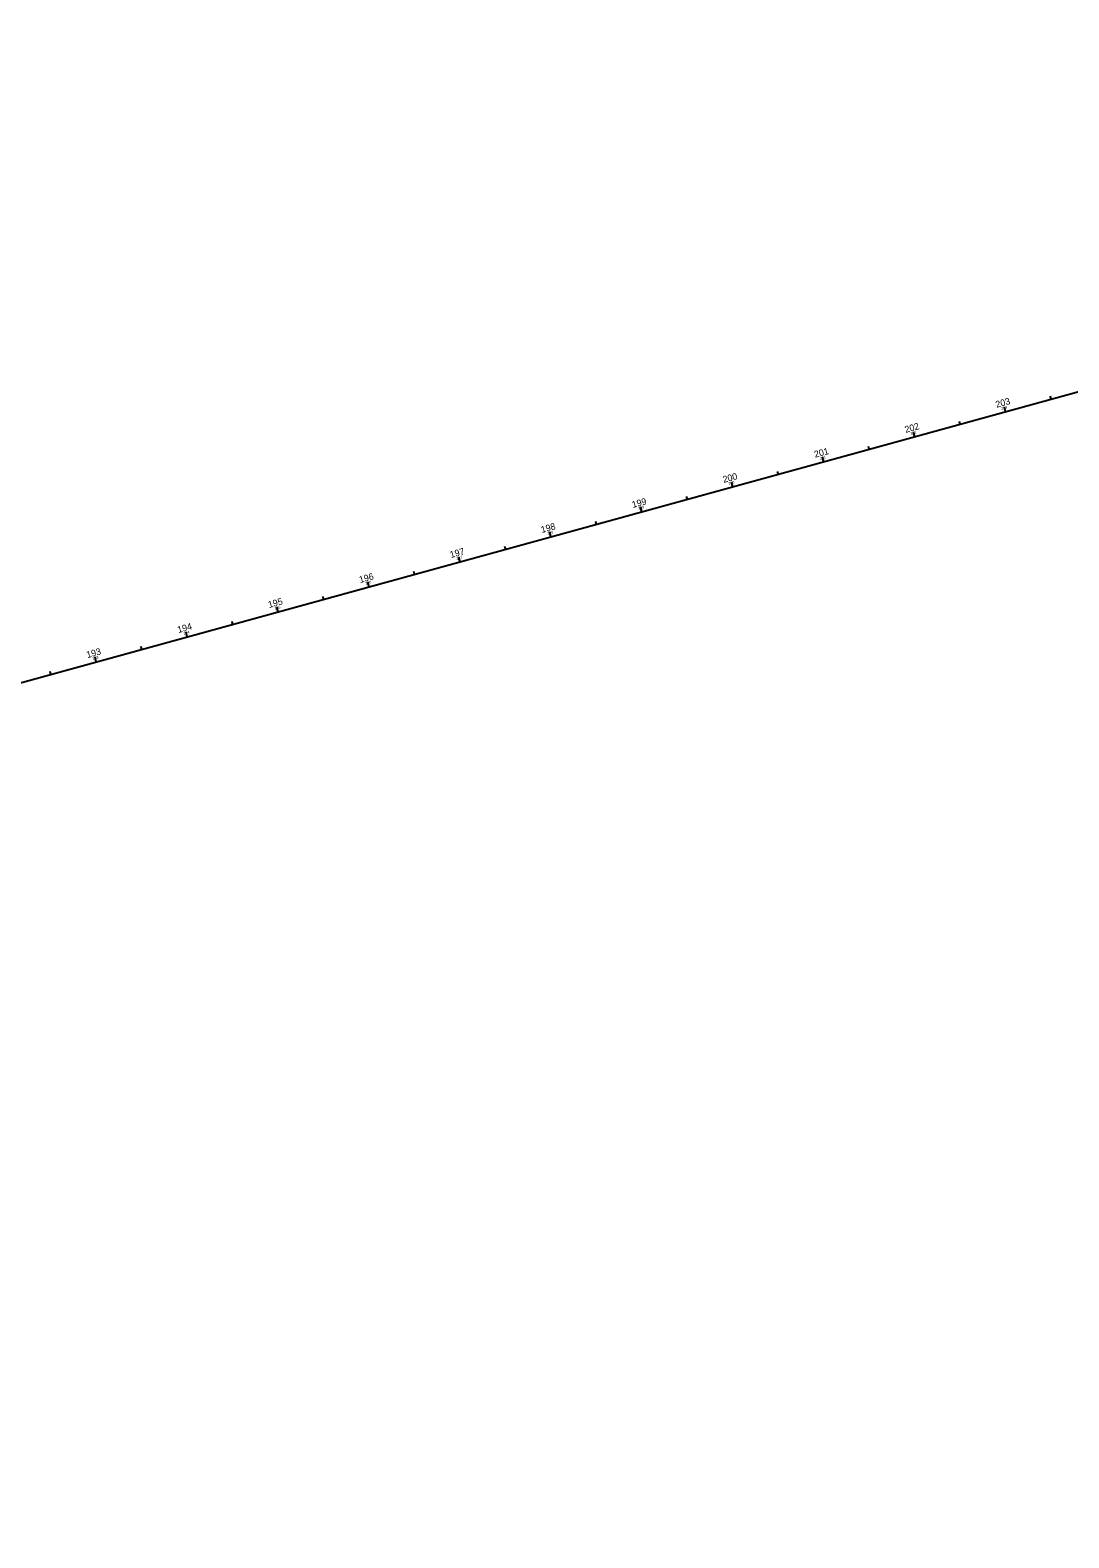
# Model space of a CAD drawing. Extents: x 2129507 to 2138391, y 657622 to 659877.
# Drawn here: x 2132841 to 2133942, y 657717 to 659316 of the extents above; entities that cross this region are included whole.
import ezdxf

# ---------------------------------------------------------------- set-up
doc = ezdxf.new("R2010")
doc.units = 0
for name, color, linetype in [('Default', 7, 'Continuous'), ('GE_X_Alignment_1000_Stations', 7, 'Continuous'), ('GE_X_Alignment_100_Stations', 7, 'Continuous'), ('GE_X_Alignment_500_Stations', 7, 'Continuous'), ('GE_X_CL_20', 7, 'Continuous'), ('MT_P_CL_20', 7, 'Continuous')]:
    doc.layers.add(name, color=color, linetype=linetype)

msp = doc.modelspace()

# ---------------------------------------------------------------- linework, layer by layer
at = {"layer": 'Default'}
for centre in [(2133875.3, 658911.3), (2133778.9, 658884.8), (2133682.5, 658858.2), (2133586, 658831.7), (2133586, 658831.7), (2133586, 658831.7), (2133489.6, 658805.2), (2133393.2, 658778.6), (2133296.8, 658752.1), (2133200.4, 658725.6), (2133104, 658699), (2133104, 658699), (2133007.6, 658672.5), (2132911.1, 658645.9)]:
    msp.add_circle(centre, 0.0000833, dxfattribs=at)
at = {"layer": 'GE_X_Alignment_1000_Stations'}
for p, q in [((2133586, 658831.7), (2133584.7, 658836.5)), ((2133104, 658699), (2133103.2, 658701.9))]:
    msp.add_line(p, q, dxfattribs=at)
at = {"layer": 'GE_X_Alignment_100_Stations'}
for p, q in [((2133875.3, 658911.3), (2133874, 658916.1)), ((2133923.5, 658924.6), (2133922.7, 658927.5)), ((2133827.1, 658898), (2133826.3, 658900.9)), ((2133778.9, 658884.8), (2133777.5, 658889.6)), ((2133730.7, 658871.5), (2133729.9, 658874.4)), ((2133682.5, 658858.2), (2133681.1, 658863.1)), ((2133586, 658831.7), (2133584.7, 658836.5)), ((2133634.3, 658845), (2133633.5, 658847.9)), ((2133537.8, 658818.4), (2133537, 658821.3)), ((2133489.6, 658805.2), (2133488.3, 658810)), ((2133441.4, 658791.9), (2133440.6, 658794.8)), ((2133345, 658765.4), (2133344.2, 658768.3)), ((2133393.2, 658778.6), (2133391.9, 658783.5)), ((2133296.8, 658752.1), (2133295.5, 658756.9)), ((2133248.6, 658738.8), (2133247.8, 658741.7)), ((2133200.4, 658725.6), (2133199.1, 658730.4)), ((2133152.2, 658712.3), (2133151.4, 658715.2)), ((2133055.8, 658685.8), (2133055, 658688.6)), ((2133104, 658699), (2133102.6, 658703.8)), ((2133007.6, 658672.5), (2133006.2, 658677.3)), ((2132959.3, 658659.2), (2132958.6, 658662.1)), ((2132911.1, 658645.9), (2132909.8, 658650.8)), ((2132862.9, 658632.7), (2132862.1, 658635.6))]:
    msp.add_line(p, q, dxfattribs=at)
at = {"layer": 'GE_X_Alignment_500_Stations'}
for p, q in [((2133875.3, 658911.3), (2133874.5, 658914.2)), ((2133778.9, 658884.8), (2133778.1, 658887.7)), ((2133682.5, 658858.2), (2133681.7, 658861.1)), ((2133586, 658831.7), (2133584.7, 658836.5)), ((2133489.6, 658805.2), (2133488.8, 658808.1)), ((2133393.2, 658778.6), (2133392.4, 658781.5)), ((2133296.8, 658752.1), (2133296, 658755)), ((2133200.4, 658725.6), (2133199.6, 658728.5)), ((2133104, 658699), (2133102.6, 658703.8)), ((2133007.6, 658672.5), (2133006.8, 658675.4)), ((2132911.1, 658645.9), (2132910.3, 658648.8))]:
    msp.add_line(p, q, dxfattribs=at)
at = {"layer": 'GE_X_CL_20'}
for p, q in [((2129536.9, 657717.3), (2135344.6, 659315.7)), ((2133875.3, 658911.3), (2133874.8, 658913.2)), ((2133923.5, 658924.6), (2133923, 658926.5)), ((2133827.1, 658898), (2133826.5, 658900)), ((2133778.9, 658884.8), (2133778.3, 658886.7)), ((2133730.7, 658871.5), (2133730.1, 658873.4)), ((2133682.5, 658858.2), (2133681.9, 658860.2)), ((2133586, 658831.7), (2133585.5, 658833.6)), ((2133634.3, 658845), (2133633.7, 658846.9)), ((2133537.8, 658818.4), (2133537.3, 658820.4)), ((2133489.6, 658805.2), (2133489.1, 658807.1)), ((2133441.4, 658791.9), (2133440.9, 658793.8)), ((2133393.2, 658778.6), (2133392.7, 658780.6)), ((2133296.8, 658752.1), (2133296.3, 658754)), ((2133345, 658765.4), (2133344.5, 658767.3)), ((2133248.6, 658738.8), (2133248.1, 658740.8)), ((2133200.4, 658725.6), (2133199.9, 658727.5)), ((2133152.2, 658712.3), (2133151.6, 658714.2)), ((2133104, 658699), (2133103.4, 658700.9)), ((2133007.6, 658672.5), (2133007, 658674.4)), ((2133055.8, 658685.8), (2133055.2, 658687.7)), ((2132959.3, 658659.2), (2132958.8, 658661.1)), ((2132911.1, 658645.9), (2132910.6, 658647.9)), ((2132862.9, 658632.7), (2132862.4, 658634.6))]:
    msp.add_line(p, q, dxfattribs=at)
at = {"layer": 'MT_P_CL_20'}
msp.add_line((2129536.9, 657717.3), (2135344.6, 659315.7), dxfattribs=at)

# ---------------------------------------------------------------- texts
at = {"layer": 'GE_X_Alignment_1000_Stations'}
msp.add_text('200', height=7, rotation=15.3886, dxfattribs=at).set_placement((2133576.4, 658835.7))
at = {"layer": 'GE_X_Alignment_100_Stations'}
for s, p in [('203', (2133865.7, 658915.3)), ('202', (2133769.3, 658888.7)), ('201', (2133673.3, 658862.3)), ('200', (2133576.4, 658835.7)), ('199', (2133480.1, 658809.1)), ('198', (2133383.6, 658782.6)), ('197', (2133287.1, 658756)), ('196', (2133190.8, 658729.5)), ('195', (2133094.3, 658703)), ('194', (2132998.1, 658676.5)), ('193', (2132901.6, 658649.9))]:
    msp.add_text(s, height=7, rotation=15.3886, dxfattribs=at).set_placement(p)
at = {"layer": 'GE_X_Alignment_500_Stations'}
for s, p in [('200', (2133576.4, 658835.7)), ('195', (2133094.3, 658703))]:
    msp.add_text(s, height=7, rotation=15.3886, dxfattribs=at).set_placement(p)
at = {"layer": 'GE_X_CL_20'}
for s, p in [('203', (2133871, 658913.2)), ('202', (2133774.6, 658886.7)), ('201', (2133678.7, 658860.3)), ('200', (2133581.7, 658833.6)), ('199', (2133486, 658807.3)), ('198', (2133389.6, 658780.8)), ('197', (2133293.1, 658754.2)), ('196', (2133196.7, 658727.7)), ('195', (2133100.3, 658701.1)), ('194', (2133003.9, 658674.6)), ('193', (2132907.5, 658648.1))]:
    msp.add_text(s, height=2.8, rotation=15.3886, dxfattribs=at).set_placement(p)

doc.saveas('drawing.dxf')
